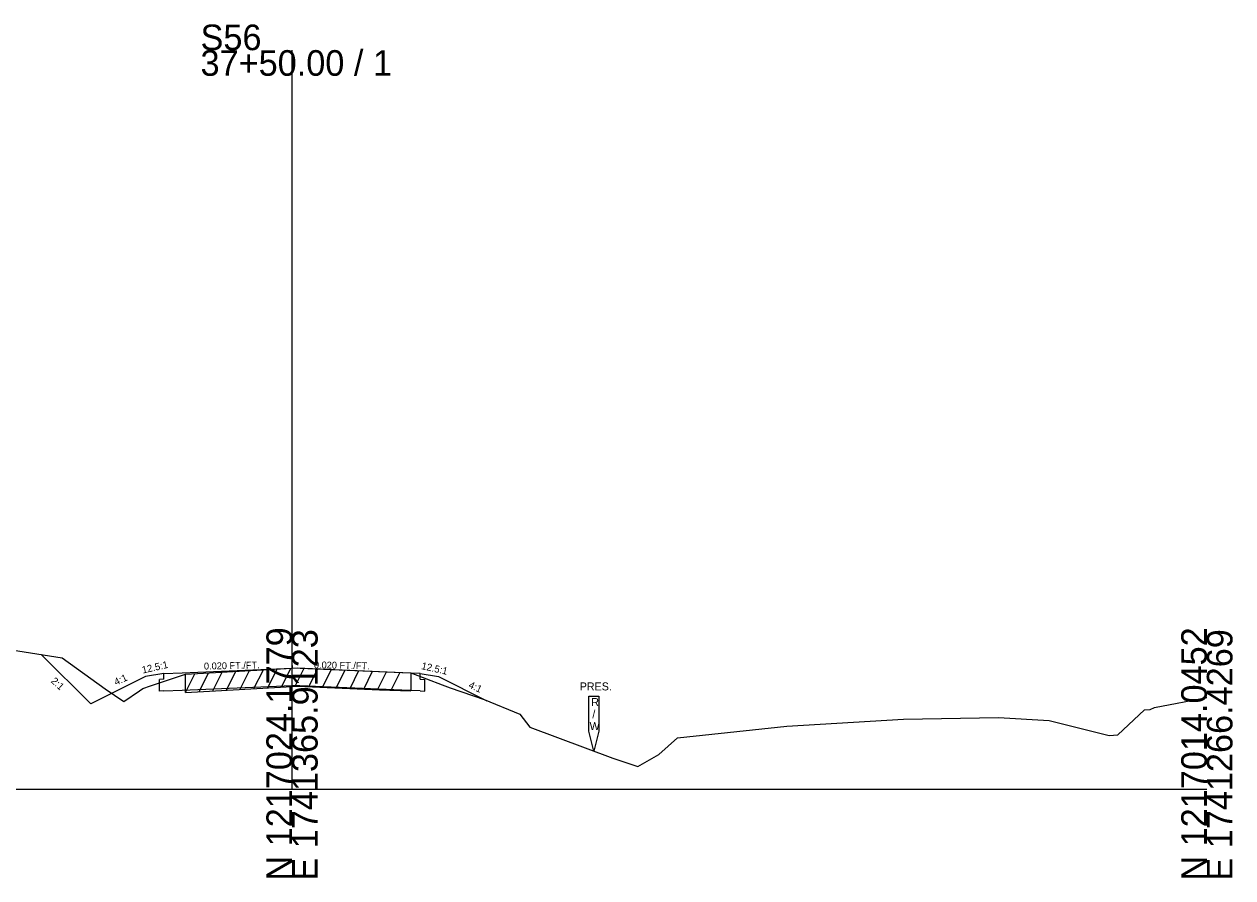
# Model space of a CAD drawing. Extents: x -26 to 1203, y -10 to 19541.
# Drawn here: x 70.7 to 202.8, y 12490.3 to 12583.6 of the extents above; entities that cross this region are included whole.
import ezdxf

# ---------------------------------------------------------------- set-up
doc = ezdxf.new("R2010")
doc.units = 0
for name, color, linetype in [('RD_GPK_XS_Cell', 7, 'Continuous'), ('RD_XS_Base', 7, 'Continuous'), ('RD_XS_EarthShd', 7, 'Continuous'), ('RD_XS_ExGround', 7, 'Continuous'), ('RD_XS_ExPaveRet', 7, 'Continuous'), ('RD_XS_ExRW', 7, 'Continuous'), ('RD_XS_Pave', 7, 'Continuous'), ('RD_XS_TX_Elev_EX', 7, 'Continuous'), ('RD_XS_TX_Slope', 7, 'Continuous')]:
    doc.layers.add(name, color=color, linetype=linetype)

msp = doc.modelspace()

# ---------------------------------------------------------------- linework, layer by layer
at = {"layer": 'RD_GPK_XS_Cell'}
for p, q in [((100, 12500), (100, 12580.77)), ((0, 12500), (100, 12500)), ((100, 12500), (200, 12500))]:
    msp.add_line(p, q, dxfattribs=at)
at = {"layer": 'RD_XS_Base'}
for p, q in [((86, 12512.01), (85.5, 12511.99)), ((85.5, 12510.72), (85.5, 12511.99)), ((86, 12512.01), (86, 12512.65)), ((114, 12512.01), (114, 12512.65)), ((114, 12512.01), (114.5, 12511.99)), ((114.5, 12510.72), (114.5, 12511.99)), ((86, 12510.74), (85.5, 12510.72)), ((86, 12510.74), (88, 12510.82)), ((88, 12510.82), (100, 12511.32)), ((112, 12510.82), (100, 12511.32)), ((114, 12510.74), (112, 12510.82)), ((114, 12510.74), (114.5, 12510.72))]:
    msp.add_line(p, q, dxfattribs=at)
at = {"layer": 'RD_XS_EarthShd'}
for p, q in [((78, 12509.31), (72.58, 12514.73)), ((84, 12512.31), (78, 12509.31)), ((86, 12512.65), (84, 12512.31)), ((114, 12512.65), (116, 12512.31)), ((116, 12512.31), (121.28, 12509.67))]:
    msp.add_line(p, q, dxfattribs=at)
at = {"layer": 'RD_XS_ExGround'}
msp.add_lwpolyline([(48.95, 12518.43), (74.86, 12514.37), (79.58, 12510.95), (81.6, 12509.59), (83.32, 12510.74), (83.69, 12511), (84.54, 12511.28), (88.34, 12512.55), (91.62, 12512.75), (100, 12513.23), (100.61, 12513.26), (109.57, 12512.85), (112.98, 12512.73), (116.42, 12511.41), (117.29, 12511.08), (121.01, 12509.78), (124.91, 12508.21), (126, 12506.78), (135.05, 12503.38), (137.8, 12502.46), (140.11, 12503.79), (142.13, 12505.59), (154.08, 12506.89), (166.85, 12507.66), (177.24, 12507.83), (182.77, 12507.5), (189.31, 12505.86), (190.28, 12505.94), (193.19, 12508.67), (193.79, 12508.71), (194.27, 12508.93), (200, 12510.02)], dxfattribs=at)
at = {"layer": 'RD_XS_ExPaveRet'}
for p, q in [((94.34, 12510.91), (95.37, 12512.97)), ((95.84, 12510.99), (96.87, 12513.05)), ((97.34, 12511.08), (98.37, 12513.14)), ((98.84, 12511.16), (99.87, 12513.22)), ((100.34, 12511.25), (101.33, 12513.23)), ((101.84, 12511.21), (102.81, 12513.16)), ((103.34, 12511.14), (104.31, 12513.09)), ((104.84, 12511.07), (105.81, 12513.02)), ((106.34, 12511), (107.31, 12512.95)), ((88.34, 12510.55), (89.37, 12512.61)), ((88.34, 12510.55), (88.34, 12512.55)), ((89.84, 12510.64), (90.87, 12512.71)), ((91.34, 12510.74), (92.37, 12512.8)), ((92.84, 12510.82), (93.87, 12512.88)), ((107.84, 12510.93), (108.81, 12512.89)), ((109.34, 12510.86), (110.32, 12512.82)), ((110.84, 12510.81), (111.82, 12512.77)), ((112.98, 12512.73), (112.98, 12510.73)), ((88.34, 12510.55), (91.62, 12510.75)), ((91.62, 12510.75), (100, 12511.23)), ((100, 12511.23), (100.61, 12511.26)), ((100.61, 12511.26), (109.57, 12510.85)), ((109.57, 12510.85), (112.98, 12510.73))]:
    msp.add_line(p, q, dxfattribs=at)
at = {"layer": 'RD_XS_ExRW'}
msp.add_lwpolyline([(132.45, 12510.17), (133.55, 12510.17), (133.55, 12506.34), (133, 12504.15), (132.45, 12506.34)], close=True, dxfattribs=at)
at = {"layer": 'RD_XS_Pave'}
for p, q in [((88, 12512.73), (100, 12513.23)), ((112, 12512.73), (100, 12513.23)), ((86, 12512.65), (88, 12512.73)), ((114, 12512.65), (112, 12512.73))]:
    msp.add_line(p, q, dxfattribs=at)

# ---------------------------------------------------------------- texts
at = {"layer": 'RD_GPK_XS_Cell'}
for s, p in [('S56', (90, 12580.77)), ('37+50.00 / 1', (90, 12577.97))]:
    msp.add_text(s, height=2.8, dxfattribs=at).set_placement(p)
for s, p in [('N 1217024.1779', (100, 12490)), ('E 1741365.9123', (102.8, 12490)), ('N 1217014.0452', (200, 12490)), ('E 1741266.4269', (202.8, 12490))]:
    msp.add_text(s, height=2.8, rotation=90, dxfattribs=at).set_placement(p)
at = {"layer": 'RD_XS_ExRW'}
for s, p in [('PRES.', (131.45, 12510.79)), ('R', (132.71, 12509.08)), ('/', (132.83, 12507.76)), ('W', (132.53, 12506.45))]:
    msp.add_text(s, height=0.875, dxfattribs=at).set_placement(p)
at = {"layer": 'RD_XS_TX_Elev_EX'}
msp.add_text('865.61', height=0.1, rotation=90, dxfattribs=at).set_placement((100.1, 12513.23))
at = {"layer": 'RD_XS_TX_Slope'}
for s, height, rotation, p in [('12.5:1', 0.778, 12.7511, (83.69, 12512.63)), ('0.020 FT./FT.', 0.7518, 1.1916, (90.38, 12513.07)), ('0.020 FT./FT.', 0.7518, 358.8084, (102.39, 12513.22)), ('12.5:1', 0.778, 347.2489, (114.09, 12513.13)), ('2:1', 0.778, 317.6004, (73.59, 12511.73)), ('4:1', 0.778, 24.919, (80.77, 12511.31)), ('4:1', 0.778, 335.081, (119.23, 12511.12))]:
    msp.add_text(s, height=height, rotation=rotation, dxfattribs=at).set_placement(p)

doc.saveas('drawing.dxf')
